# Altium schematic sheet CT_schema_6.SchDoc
size 302 x 256 mm
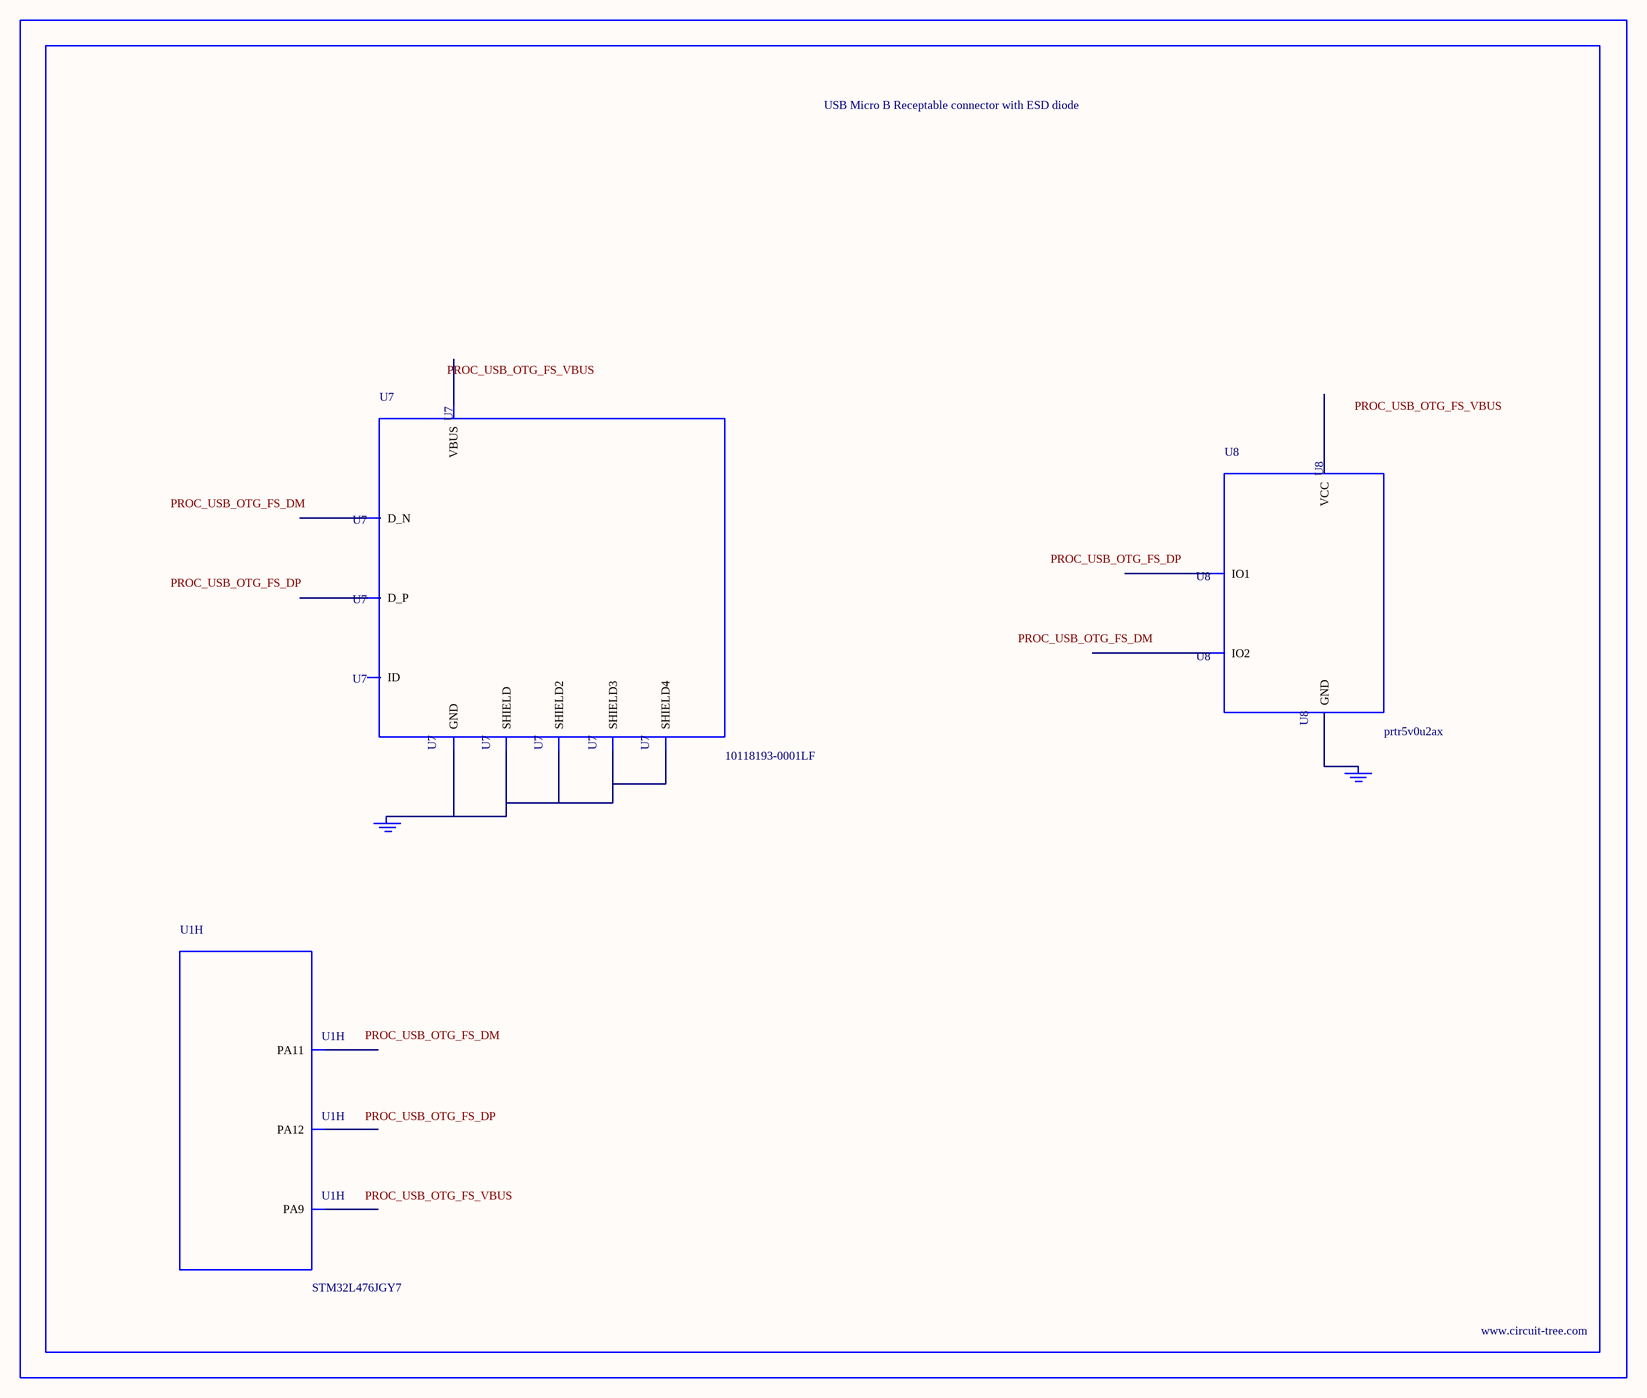
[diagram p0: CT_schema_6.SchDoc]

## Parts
BORDER5  (no value)
GND_INSTANCE_5_0  (no value)
GND_INSTANCE_5_1  (no value)
U1  STM32L476JGY7  [WLCSP72]  (part H of 8)
U7  10118193-0001LF  [FCI_10118193-0001LF]
U8  prtr5v0u2ax  [SOT143B]

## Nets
NetGND_INSTANCE_5_0_0: GND_INSTANCE_5_0.0(GND) U7.5(GND) U7.6(SHIELD) U7.7(SHIELD2) U7.8(SHIELD3) U7.9(SHIELD4)
NetGND_INSTANCE_5_1_0: GND_INSTANCE_5_1.0(GND) U8.1(GND)

Not connected (* = marked no-connect by the designer): U1 C1(PA12) D1(PA11) E3(PA9); U7 1(VBUS) 2(D_N) 3(D_P) 4(ID); U8 2(IO1) 3(IO2) 4(VCC)

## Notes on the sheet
- Labels drawn without touching a wire or pin: PROC_USB_OTG_FS_DM, PROC_USB_OTG_FS_DP, PROC_USB_OTG_FS_VBUS

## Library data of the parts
BORDER5 = BORDER_PAGE5
GND_INSTANCE_5_0 GND_INSTANCE_5_1 = GND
